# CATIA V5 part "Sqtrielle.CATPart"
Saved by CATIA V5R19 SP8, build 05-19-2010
Part number: Sqtrielle
Publications: "Droite.3", "Droite.1", "Droite.2", "X", "X1"
Bounding box of the stored display mesh (mm): x -290 to 0, y 0 to 20, z 0 to 0
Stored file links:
  F:\Travail\2e année\IAO\Projetsave\Sqtrielle.CATPart
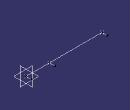
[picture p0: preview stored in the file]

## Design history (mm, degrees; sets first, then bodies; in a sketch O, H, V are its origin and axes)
Set1
  Point1: (0, 0, 0)
  Line1: type Normal, RefPoint Point1, RefSkin zx-plane, Start 0, End 20
  Point2: (-90, 0, 0), relative to Point1
  Point3: (-290, 0, 0)
  Line2: type PtDir, RefPoint Point3, Direction zx-plane, Start 0, End 20
  Line3: type PtDir, RefPoint Point2, Direction zx-plane, Start 0, End 20
  Line4: type PtPt, FirstPoint Point3, SecondPoint Point1
Body1 (main body)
